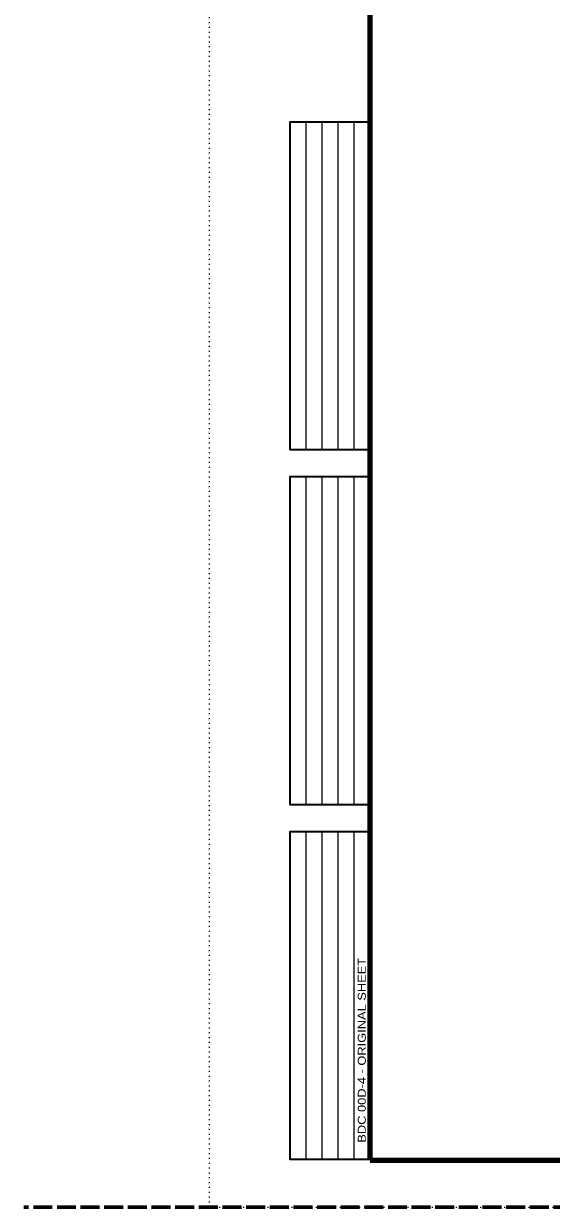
# Model space of a CAD drawing. Extents: x 312583 to 312854, y 144419 to 144597.
# Drawn here: x 312583.5 to 312633.7, y 144418.6 to 144531.2 of the extents above; entities that cross this region are included whole.
import ezdxf

# ---------------------------------------------------------------- set-up
doc = ezdxf.new("R2010")
doc.units = 0
doc.header["$LTSCALE"] = 0.3
doc.linetypes.add('DOTTED', pattern=[1.5, 0.3, -1.2])
doc.linetypes.add('LONG_DASHED', pattern=[7.5, 6, -1.5])
for name, color, linetype, lineweight in [('1', 7, 'Continuous', 40), ('62', 7, 'DOTTED', 13), ('63', 7, 'LONG_DASHED', 60)]:
    doc.layers.add(name, color=color, linetype=linetype, lineweight=lineweight)

msp = doc.modelspace()

# ---------------------------------------------------------------- linework, layer by layer
at = {"layer": '1', "lineweight": 25}
for p, q in [((312610.4087, 144490.6573), (312610.4087, 144521.8756)), ((312611.9315, 144490.6573), (312611.9315, 144521.8756)), ((312613.4543, 144490.6573), (312613.4543, 144521.8756)), ((312614.9772, 144490.6573), (312614.9772, 144521.8756)), ((312610.4087, 144456.901), (312610.4087, 144488.1192)), ((312611.9315, 144456.901), (312611.9315, 144488.1192)), ((312613.4543, 144456.901), (312613.4543, 144488.1192)), ((312614.9772, 144456.901), (312614.9772, 144488.1192)), ((312610.4087, 144423.1446), (312610.4087, 144454.3629)), ((312611.9315, 144423.1446), (312611.9315, 144454.3629)), ((312613.4543, 144423.1446), (312613.4543, 144454.3629)), ((312614.9772, 144423.1446), (312614.9772, 144454.3629))]:
    msp.add_line(p, q, dxfattribs=at)
at = {"layer": '1', "lineweight": 158}
msp.add_line((312616.5, 144423.0846), (312849, 144423.0846), dxfattribs=at)
msp.add_lwpolyline([(312616.5, 144423.1446), (312616.5, 144585.0846), (312849, 144585.0846)], dxfattribs=at)
at = {"layer": '1', "lineweight": 35}
for points in [[(312616.5, 144490.6573), (312608.8858, 144490.6573), (312608.8858, 144521.8756), (312616.5, 144521.8756)], [(312616.5, 144456.901), (312608.8858, 144456.901), (312608.8858, 144488.1192), (312616.5, 144488.1192)], [(312616.5, 144423.1446), (312608.8858, 144423.1446), (312608.8858, 144454.3629), (312616.5, 144454.3629)]]:
    msp.add_lwpolyline(points, dxfattribs=at)
at = {"layer": '62'}
msp.add_line((312601.2, 144418.5846), (312601.2, 144596.7846), dxfattribs=at)
msp.add_lwpolyline([(312601.2, 144418.5846), (312853.5, 144418.5846), (312853.5, 144596.7846)], dxfattribs=at)
at = {"layer": '63'}
msp.add_line((312851.75, 144418.5846), (312583.526, 144418.5846), dxfattribs=at)

# ---------------------------------------------------------------- texts
at = {"layer": '1', "width": 1.2}
msp.add_text('BDC 00D-4 - ORIGINAL SHEET', height=0.7614, rotation=90, dxfattribs=at).set_placement((312616.0832, 144424.7374))

doc.saveas('drawing.dxf')
